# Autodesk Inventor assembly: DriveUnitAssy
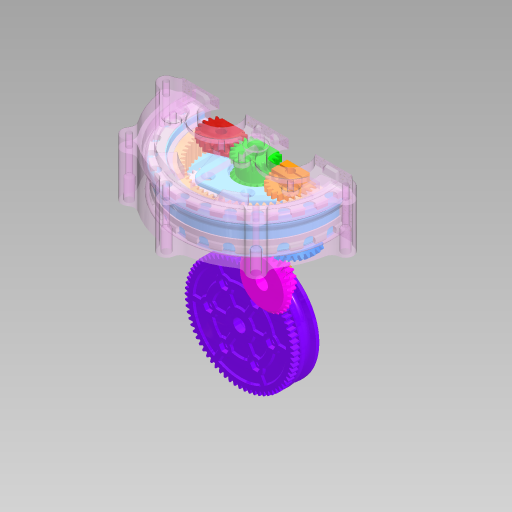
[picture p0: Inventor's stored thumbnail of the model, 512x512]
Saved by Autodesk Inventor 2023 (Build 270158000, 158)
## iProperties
Created: 2024-05
Part Number: DriveUnitAssy
Document SubType Name: Assembly
Designer: kumagai
Author: kumagai
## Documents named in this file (9)
- X:\Develop\CAD\NakataOmni\DriveUnitR3\DriveUnitAssy.iam
- X:\Develop\CAD\NakataOmni\DriveUnitR3\LowerCase.ipt
- X:\Develop\CAD\NakataOmni\DriveUnitR3\StreerBaseAssy.iam
- X:\Develop\CAD\NakataOmni\DriveUnitR3\UpperCase.ipt
- X:\Develop\CAD\NakataOmni\DriveUnitR3\BearingSeal.ipt
- X:\Develop\CAD\NakataOmni\DriveUnitR3\MotorDriveGear.ipt
- X:\Develop\CAD\NakataOmni\DriveUnitR3\WheelUnitAssy.iam
- X:\Develop\CAD\NakataOmni\DriveUnitR3\Ratainer_SB_UC.ipt
- X:\Develop\CAD\NakataOmni\DriveUnitR3\Ratainer_SB_LC.ipt
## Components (9 placed, 8 different names)
1. LowerCase:1 — メイト:1, フラッシュ:1, フラッシュ:2, メイト:2, フラッシュ:3, フラッシュ:4, メイト:12
2. StreerBaseAssy:1 [sub-assembly] — メイト:1, メイト:3, フラッシュ:5, フラッシュ:6, メイト:7, メイト:8, メイト:9, メイト:10, メイト:11
3. UpperCase:1 — フラッシュ:1, フラッシュ:2, メイト:2, メイト:3, メイト:4, メイト:5, メイト:6
4. BearingSeal:1 — フラッシュ:3, フラッシュ:4, メイト:4
5. 平歯車1:1 — メイト:5, フラッシュ:6
6. 平歯車1:2 — メイト:6, フラッシュ:5
7. WheelUnitAssy:1 [sub-assembly] — メイト:7, メイト:8, メイト:9
8. Ratainer_SB_UC:1 — メイト:10
9. Ratainer_SB_LC:1 — メイト:11, メイト:12
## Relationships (18: Mate 12, Flush 6)
- メイト:1 [Mate]: LowerCase:1 ↔ StreerBaseAssy:1
- フラッシュ:1 [Flush]: LowerCase:1 ↔ UpperCase:1
- フラッシュ:2 [Flush]: LowerCase:1 ↔ UpperCase:1
- メイト:2 [Mate]: LowerCase:1 ↔ UpperCase:1
- メイト:3 [Mate]: StreerBaseAssy:1 ↔ UpperCase:1
- フラッシュ:3 [Flush]: LowerCase:1 ↔ BearingSeal:1
- フラッシュ:4 [Flush]: LowerCase:1 ↔ BearingSeal:1
- メイト:4 [Mate]: UpperCase:1 ↔ BearingSeal:1
- メイト:5 [Mate]: UpperCase:1 ↔ 平歯車1:1
- メイト:6 [Mate]: UpperCase:1 ↔ 平歯車1:2
- フラッシュ:5 [Flush]: StreerBaseAssy:1 ↔ 平歯車1:2
- フラッシュ:6 [Flush]: StreerBaseAssy:1 ↔ 平歯車1:1
- メイト:7 [Mate]: StreerBaseAssy:1 ↔ WheelUnitAssy:1
- メイト:8 [Mate]: StreerBaseAssy:1 ↔ WheelUnitAssy:1
- メイト:9 [Mate]: StreerBaseAssy:1 ↔ WheelUnitAssy:1
- メイト:10 [Mate]: StreerBaseAssy:1 ↔ Ratainer_SB_UC:1
- メイト:11 [Mate]: StreerBaseAssy:1 ↔ Ratainer_SB_LC:1
- メイト:12 [Mate]: LowerCase:1 ↔ Ratainer_SB_LC:1
